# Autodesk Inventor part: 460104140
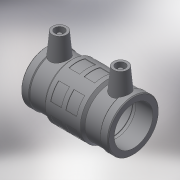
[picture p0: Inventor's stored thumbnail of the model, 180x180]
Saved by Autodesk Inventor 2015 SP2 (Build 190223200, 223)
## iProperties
Created: 2017-06
Part Number: 460104140
Material: Generic
Description: PLASSON LIGHTFIT COUPLER 140
Document SubType Name: Modeling
Designer: KIM
Mass: 89.5427 g
Surface Area: 304.58 cm^2
Volume: 89.5427 cm^3
Density: 1 g/cm^3
Appearance: Default
Author: KIM
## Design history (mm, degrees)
derived "460104.ipt"
feature "Solid1::460104.ipt"
tag "TaggingFeature1"
body "Solid1"
other parameters: "d13" = 182, "d14" = 17.6296, "d15" = 89, "d16" = 89, "d17" = 138.6, "d19" = 3.52592, "d20" = 168 deg, "d22" = 156.98, "d23" = 167, "d24" = 152.2706, "d25" = 135 deg, "d26" = 72.8, "d27" = 135 deg, "d29" = 94, "d35" = 15, "d39" = 5 deg, "d44" = 4, "d46" = 14, "d47" = 0, "d52" = 163.66, "d53" = 9.1, "d54" = 9.1, "d55" = 9.1, "d56" = 35 deg, "d58" = 360 deg, "d60" = 17.8, "d61" = 135 deg, "d62" = 76.44, "d63" = 3, "d64" = 0, "L_" = 182, "L_1" = 89, "D_" = 167, "A_" = 94, "d_2" = 12
